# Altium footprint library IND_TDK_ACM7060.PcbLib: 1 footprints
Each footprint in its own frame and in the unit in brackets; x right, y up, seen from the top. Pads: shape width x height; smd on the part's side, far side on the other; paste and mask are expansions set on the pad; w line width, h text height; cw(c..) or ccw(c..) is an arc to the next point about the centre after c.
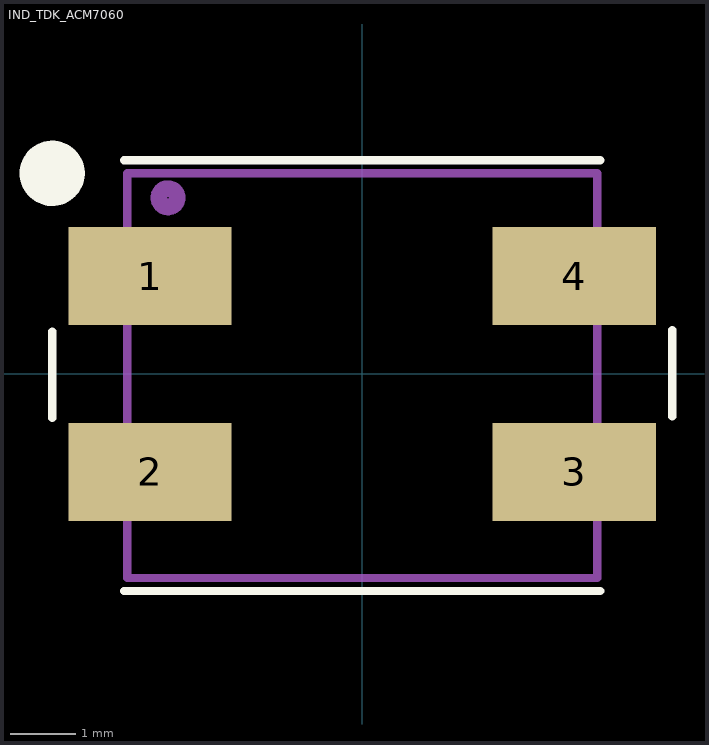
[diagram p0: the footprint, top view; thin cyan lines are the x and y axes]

## IND_TDK_ACM7060 [mm] "TDK Common Mode EMI Filter 7mmx6mm"
height 3.5
pads (4):
  rect 2.5x1.5 smd: 1(-3.25,1.5) 2(-3.25,-1.5) 3(3.25,-1.5) 4(3.25,1.5)
Top Overlay:
  circle w0.5: c-4.75,3.075 r0.25
  lines w0.127: -4.75,-0.675 -4.75,0.65 ; -3.65,-3.325 3.65,-3.325 ; -3.65,3.275 3.65,3.275 ; 4.75,-0.65 4.75,0.675
M5 Assembly Top:
  circle w0.254: c-2.975,2.7 r0.141
  lines w0.127: -3.6,-3.125 3.6,-3.125 3.6,3.075 -3.6,3.075 -3.6,-3.125
  text ".Designator" at -2.2,-0.475 h1.02
3D body: height 3.5, standoff 0, extent -3.599,-3.124 3.599,3.074
3D body: height 3.55, standoff 3.4, extent -3.116,2.559 -2.834,2.841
